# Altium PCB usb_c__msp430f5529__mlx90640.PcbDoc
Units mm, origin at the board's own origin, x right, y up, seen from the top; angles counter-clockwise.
Board outline 82 x 52 mm, 2 copper layers (Top, Bottom), stack 0 mm thick; 30 components, 24 nets, 178 pads, 53 vias.
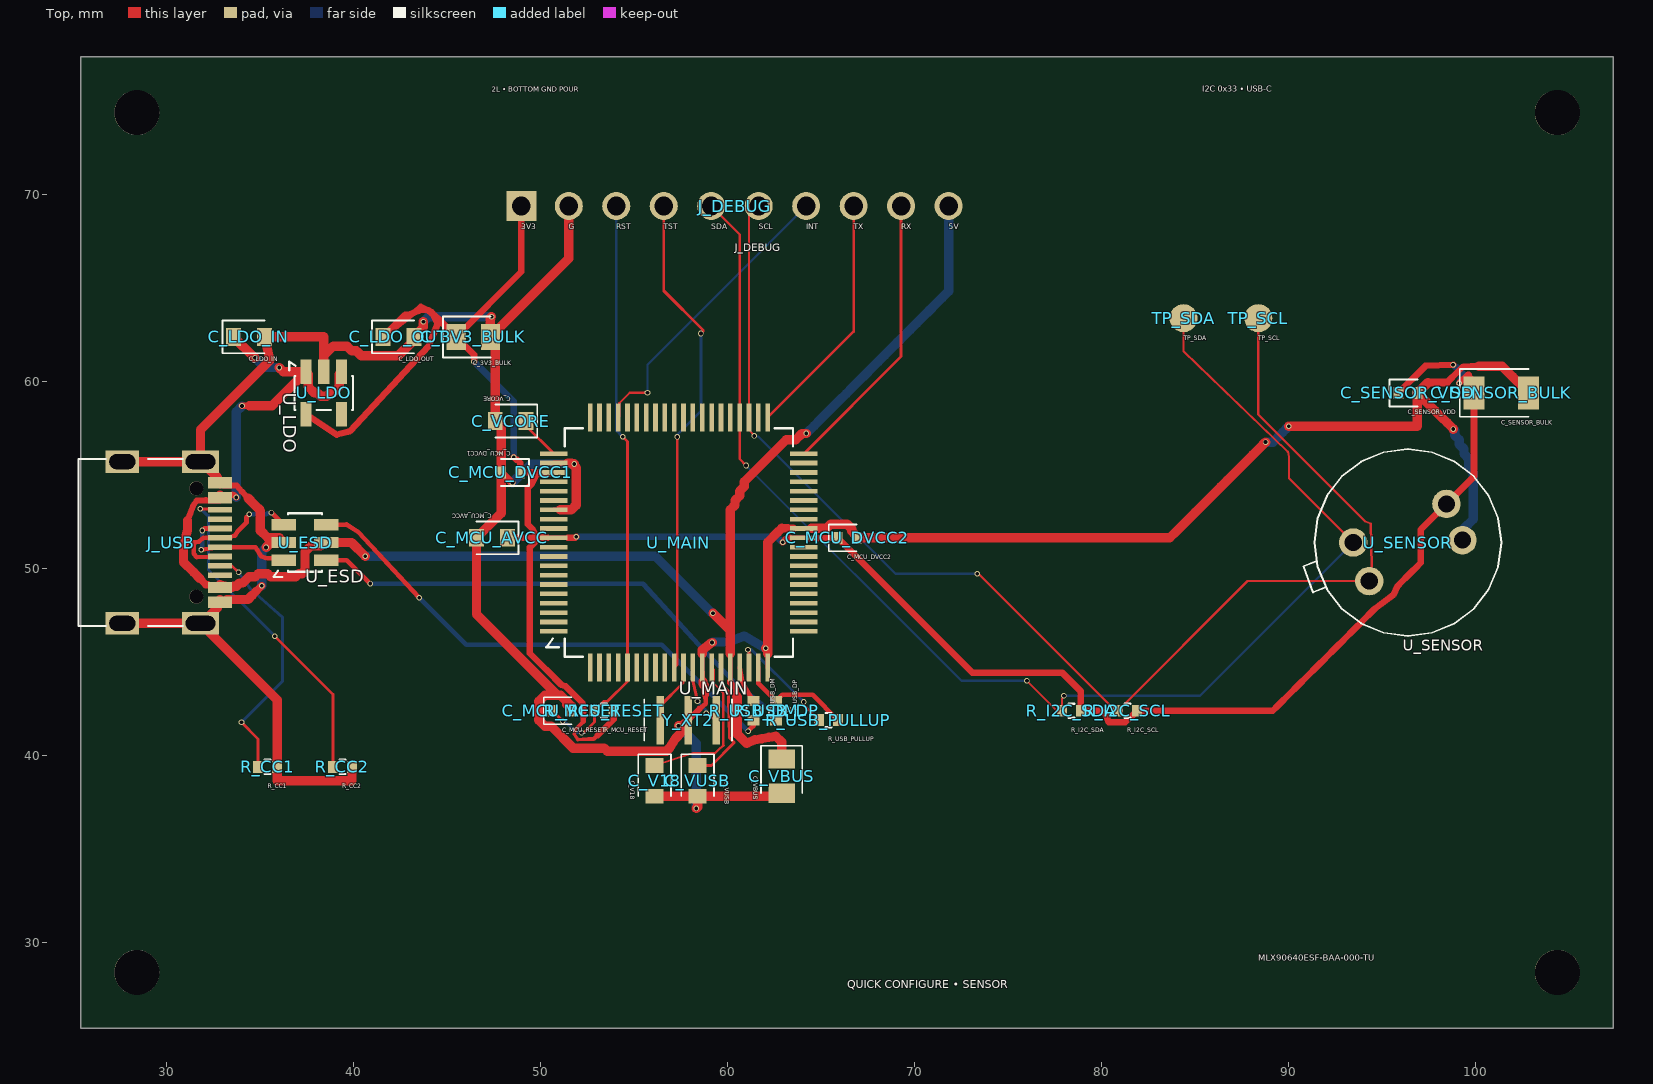
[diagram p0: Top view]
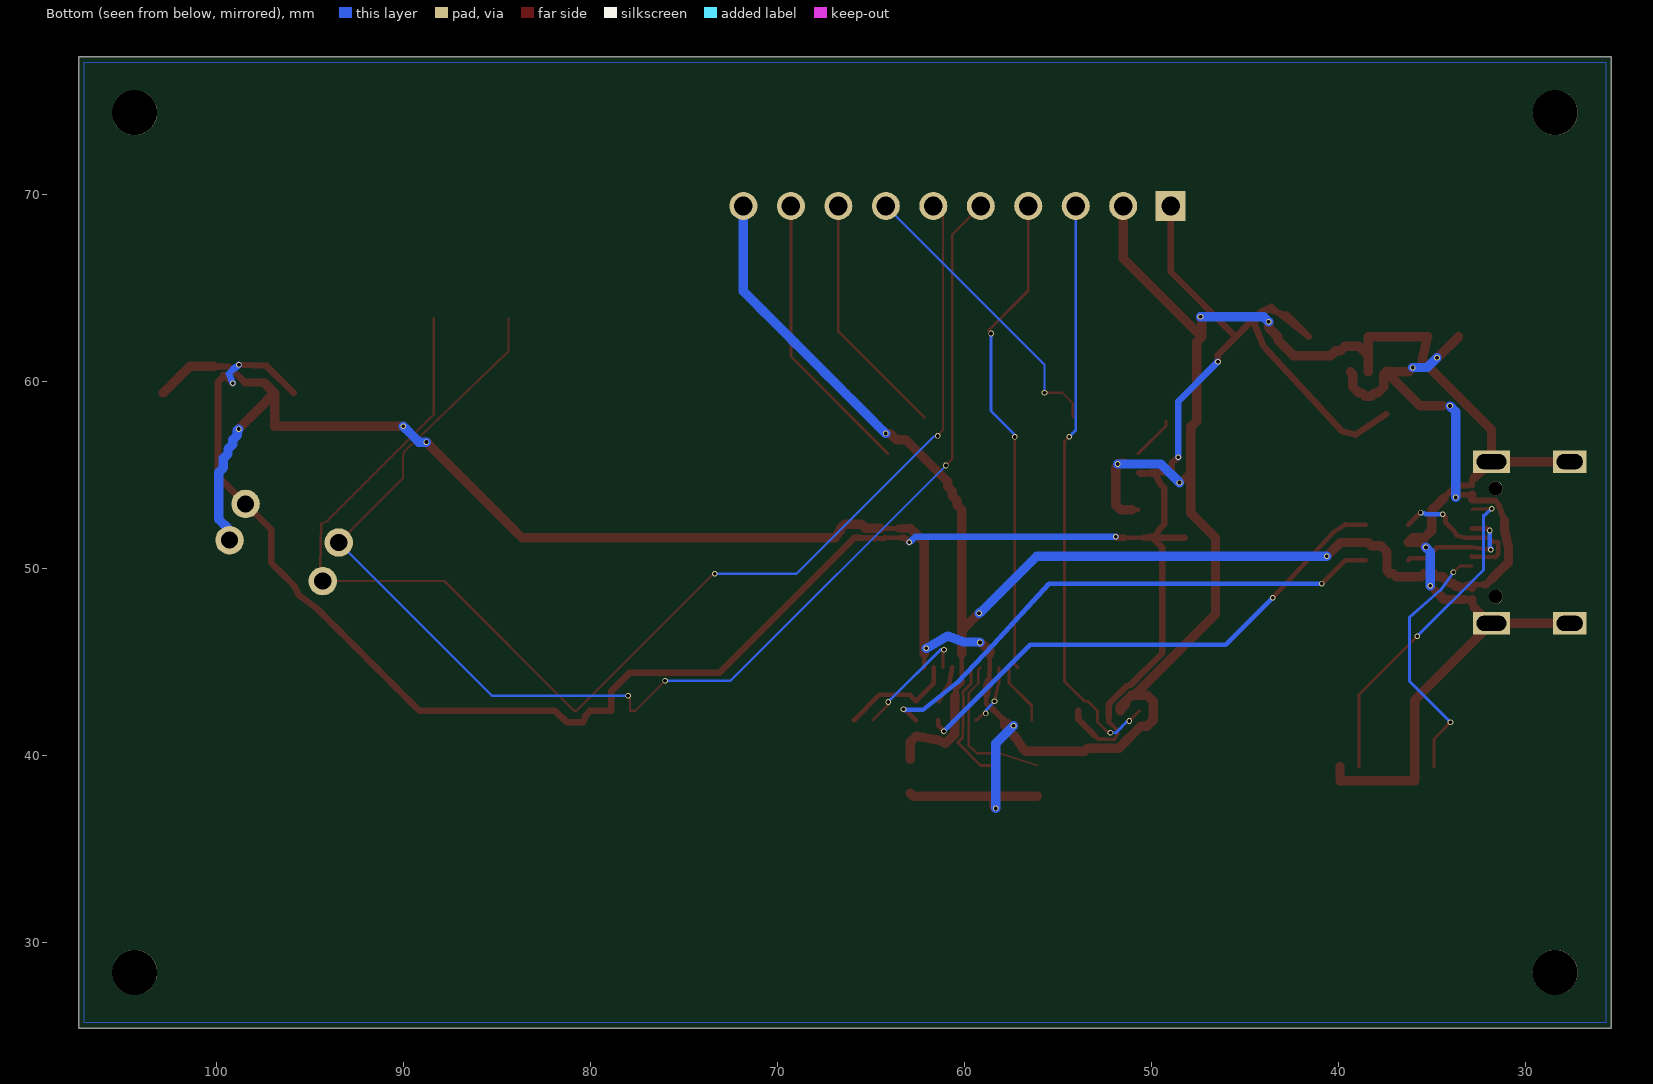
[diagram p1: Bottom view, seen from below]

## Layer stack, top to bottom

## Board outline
25.4,77.4 107.4,77.4 107.4,25.4 25.4,25.4

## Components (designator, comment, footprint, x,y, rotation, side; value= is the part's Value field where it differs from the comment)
C_3V3_BULK "" TSCIRCUIT-2.8500x1.4000mm 46.4,62.4 r0 top
C_LDO_IN "" TSCIRCUIT-2.4500x0.9500mm 34.4,62.4 r0 top
C_LDO_OUT "" TSCIRCUIT-2.4500x0.9500mm 42.4,62.4 r0 top
C_MCU_AVCC "" TSCIRCUIT-2.4500x0.9500mm 47.4,51.65 r180 top
C_MCU_DVCC1 "" TSCIRCUIT-1.5600x0.6400mm 48.4,55.15 r180 top
C_MCU_DVCC2 "" TSCIRCUIT-1.5600x0.6400mm 66.4,51.65 r0 top
C_MCU_RESET "" TSCIRCUIT-1.5600x0.6400mm 51.15,42.4 r0 top
C_SENSOR_BULK "" TSCIRCUIT-4.0500x1.7500mm 101.4,59.4 r0 top
C_SENSOR_VDD "" TSCIRCUIT-1.5600x0.6400mm 96.4,59.4 r0 top
C_V18 "" TSCIRCUIT-0.9500x2.4500mm 56.1,38.65 r270 top
C_VBUS "" TSCIRCUIT-1.4000x2.8500mm 62.9,38.9 r270 top
C_VCORE "" TSCIRCUIT-2.4500x0.9500mm 48.4,57.9 r180 top
C_VUSB "" TSCIRCUIT-0.9500x2.4500mm 58.4,38.65 r270 top
J_DEBUG "" TSCIRCUIT-24.3600x1.5000mm 60.4,69.4 r0 top
J_USB "" TSCIRCUIT-6.7732x9.8502mm 30.113,51.4 r90 top
R_CC1 "" TSCIRCUIT-1.5600x0.6400mm 35.4,39.4 r0 top
R_CC2 "" TSCIRCUIT-1.5600x0.6400mm 39.4,39.4 r0 top
R_I2C_SCL "" TSCIRCUIT-1.5600x0.6400mm 81.4,42.4 r0 top
R_I2C_SDA "" TSCIRCUIT-1.5600x0.6400mm 78.4,42.4 r0 top
R_MCU_RESET "" TSCIRCUIT-1.5600x0.6400mm 53.4,42.4 r0 top
R_USB_DM "" TSCIRCUIT-0.6400x1.5600mm 61.4,42.4 r90 top
R_USB_DP "" TSCIRCUIT-0.6400x1.5600mm 62.6,42.4 r90 top
R_USB_PULLUP "" TSCIRCUIT-1.5600x0.6400mm 65.4,41.9 r0 top
TP_SCL "" TSCIRCUIT-1.5000x1.5000mm 88.4,63.4 r0 top
TP_SDA "" TSCIRCUIT-1.5000x1.5000mm 84.4,63.4 r0 top
U_ESD "" TSCIRCUIT-3.6000x2.5000mm 37.4,51.4 r0 top
U_LDO "" TSCIRCUIT-2.5000x3.6000mm 38.4,59.4 r270 top
U_MAIN "" TSCIRCUIT-14.8500x14.8500mm 57.4,51.4 r0 top
U_SENSOR "" TSCIRCUIT-7.3640x5.6538mm 96.4,51.4 r0 top
Y_XT2 "" TSCIRCUIT-3.4000x2.6000mm 57.9,41.9 r270 top

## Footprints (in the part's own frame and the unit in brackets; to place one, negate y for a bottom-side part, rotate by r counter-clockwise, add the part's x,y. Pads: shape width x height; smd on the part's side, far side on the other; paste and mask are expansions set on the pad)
TSCIRCUIT-0.6400x1.5600mm [mm]
  rect 0.54x0.64 smd: 1(-0.51,0) 2(0.51,0)
  silkscreen extent -0.15,-0.38 0.15,0.38
TSCIRCUIT-0.9500x2.4500mm [mm]
  rect 0.8x0.95 smd: 1(-0.825,0) 2(0.825,0)
  silkscreen extent -1.43,-0.87 0.82,0.87
TSCIRCUIT-1.4000x2.8500mm [mm]
  rect 1.025x1.4 smd: 1(-0.913,0) 2(0.913,0)
  silkscreen extent -1.62,-1.1 0.91,1.1
TSCIRCUIT-1.5000x1.5000mm [mm]
  round 1.5 smd: 1(0,0)
TSCIRCUIT-1.5600x0.6400mm [mm]
  rect 0.54x0.64 smd: 1(-0.51,0) 2(0.51,0)
  silkscreen extent -0.98,-0.72 0.51,0.72
TSCIRCUIT-2.4500x0.9500mm [mm]
  rect 0.8x0.95 smd: 1(-0.825,0) 2(0.825,0)
  silkscreen extent -1.43,-0.87 0.82,0.87
TSCIRCUIT-2.5000x3.6000mm [mm]
  rect 1.325x0.6 smd: 1(-1.137,-0.95) 2(-1.137,0) 3(-1.137,0.95) 4(1.138,0.95) 5(1.138,-0.95)
  silkscreen extent -1.69,-1.84 0.91,1.56
TSCIRCUIT-2.8500x1.4000mm [mm]
  rect 1.025x1.4 smd: 1(-0.913,0) 2(0.913,0)
  silkscreen extent -1.63,-1.1 0.91,1.1
TSCIRCUIT-3.4000x2.6000mm [mm]
  rect 2.6x0.4 smd: 1(0,1.5) 2(0,0) 3(0,-1.5)
  silkscreen extent -1.1,-2.35 1.1,2.35
TSCIRCUIT-3.6000x2.5000mm [mm]
  rect 1.325x0.6 smd: 1(-1.137,-0.95) 2(-1.137,0) 3(-1.137,0.95) 4(1.138,0.95) 5(1.138,0) 6(1.138,-0.95)
  silkscreen extent -1.69,-1.84 0.91,1.56
TSCIRCUIT-4.0500x1.7500mm [mm]
  rect 1.125x1.75 smd: 1(-1.463,0) 2(1.462,0)
  silkscreen extent -2.22,-1.28 1.46,1.27
TSCIRCUIT-6.7732x9.8502mm [mm]
  rect 0.3x1.3 smd: 1(-3.35,-2.737) 2(-3.05,-2.737) 3(-2.55,-2.737) 4(-2.25,-2.737) 5(-1.75,-2.737) 6(-1.25,-2.737) 7(-0.75,-2.737) 8(-0.25,-2.737) 9(0.25,-2.737) 10(0.75,-2.737) 11(1.25,-2.737) 12(1.75,-2.737) 13(2.55,-2.737) 14(2.25,-2.737) 15(3.35,-2.737) 16(3.05,-2.737)
  rect 1.2x2 hole 0.8 slot 1.6 at 90 deg: 17(-4.325,-1.693) 18(4.325,-1.693)
  rect 1.2x1.8 hole 0.8 slot 1.4 at 90 deg: 19(4.325,2.487) 20(-4.325,2.487)
  round 0.75 hole 0.75 unplated: NPTH-1(-2.9,-1.468) NPTH-2(2.9,-1.468)
  silkscreen extent -4.47,-0.75 4.47,4.83
TSCIRCUIT-7.3640x5.6538mm [mil]
  round 60 hole 36: 1(-114.96,0) 2(81.29,81.29) 3(114.96,5) 4(-81.3,-81.3)
  silkscreen extent -220,-197 197,197
TSCIRCUIT-14.8500x14.8500mm [mm]
  rect 1.475x0.25 smd: 1(-6.687,-4.75) 2(-6.687,-4.25) 3(-6.687,-3.75) 4(-6.687,-3.25) 5(-6.687,-2.75) 6(-6.687,-2.25) 7(-6.687,-1.75) 8(-6.687,-1.25) 9(-6.687,-0.75) 10(-6.687,-0.25) 11(-6.687,0.25) 12(-6.687,0.75) 13(-6.687,1.25) 14(-6.687,1.75) 15(-6.687,2.25) 16(-6.687,2.75) 17(-6.687,3.25) 18(-6.687,3.75) 19(-6.687,4.25) 20(-6.687,4.75) 41(6.687,4.75) 42(6.687,4.25) 43(6.687,3.75) 44(6.687,3.25) 45(6.687,2.75) 46(6.687,2.25) 47(6.687,1.75) 48(6.687,1.25) 49(6.687,0.75) 50(6.687,0.25) 51(6.687,-0.25) 52(6.687,-0.75) 53(6.687,-1.25) 54(6.687,-1.75) 55(6.687,-2.25) 56(6.687,-2.75) 57(6.687,-3.25) 58(6.687,-3.75) 59(6.687,-4.25) 60(6.687,-4.75)
  rect 0.25x1.475 smd: 21(-4.75,6.687) 22(-4.25,6.687) 23(-3.75,6.687) 24(-3.25,6.687) 25(-2.75,6.687) 26(-2.25,6.687) 27(-1.75,6.687) 28(-1.25,6.687) 29(-0.75,6.687) 30(-0.25,6.687) 31(0.25,6.687) 32(0.75,6.687) 33(1.25,6.687) 34(1.75,6.687) 35(2.25,6.687) 36(2.75,6.687) 37(3.25,6.687) 38(3.75,6.687) 39(4.25,6.687) 40(4.75,6.687) 61(4.75,-6.687) 62(4.25,-6.687) 63(3.75,-6.687) 64(3.25,-6.687) 65(2.75,-6.687) 66(2.25,-6.687) 67(1.75,-6.687) 68(1.25,-6.687) 69(0.75,-6.687) 70(0.25,-6.687) 71(-0.25,-6.687) 72(-0.75,-6.687) 73(-1.25,-6.687) 74(-1.75,-6.687) 75(-2.25,-6.687) 76(-2.75,-6.687) 77(-3.25,-6.687) 78(-3.75,-6.687) 79(-4.25,-6.687) 80(-4.75,-6.687)
  silkscreen extent -7.09,-6.11 6.11,6.11
TSCIRCUIT-24.3600x1.5000mm [mm]
  rect 1.6x1.6 hole 1: 1(-11.43,0)
  round 1.5 hole 1: 2(-8.89,0) 3(-6.35,0) 4(-3.81,0) 5(-1.27,0) 6(1.27,0) 7(3.81,0) 8(6.35,0) 9(8.89,0) 10(11.43,0)

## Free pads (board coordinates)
  round 2.4 hole 2.4 unplated: NPTH-3(28.4,28.4) NPTH-4(104.4,28.4) NPTH-5(28.4,74.4) NPTH-6(104.4,74.4)

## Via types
v1: diameter 0.3, hole 0.2, Top to Bottom, 53 vias

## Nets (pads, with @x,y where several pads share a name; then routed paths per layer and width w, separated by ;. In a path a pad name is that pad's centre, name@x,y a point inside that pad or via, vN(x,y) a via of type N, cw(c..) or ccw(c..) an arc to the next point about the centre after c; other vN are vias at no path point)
".J_DEBUG > .pin4 to .U_MAIN > .pin71": J_DEBUG.4 U_MAIN.71 | length 26.2
  Top w0.15: J_DEBUG.4 56.59,64.866 58.687,62.769 58.687,62.688 v1(58.58,62.581) ; U_MAIN.71 57.311,44.873 v1(57.311,57.048)
  Bottom w0.15: v1(57.311,57.048) 57.275,57.084 57.275,57.123 58.58,58.428 v1(58.58,62.581)
".J_DEBUG > .pin8 to .U_MAIN > .pin40": J_DEBUG.8 U_MAIN.40 | length 13.2
  Top w0.15: U_MAIN.40 66.75,62.687 J_DEBUG.8
".J_DEBUG > .pin9 to .U_MAIN > .pin41": J_DEBUG.9 U_MAIN.41 | length 15.4
  Top w0.15: U_MAIN.41 69.29,61.352 J_DEBUG.9
GND: C_3V3_BULK.2 C_LDO_IN.2 C_LDO_OUT.2 C_MCU_AVCC.2 C_MCU_DVCC1.2 C_MCU_DVCC2.2 C_MCU_RESET.2 C_SENSOR_BULK.2 C_SENSOR_VDD.2 C_V18.2 C_VBUS.2 C_VCORE.2 C_VUSB.2 J_DEBUG.2 J_USB.1 J_USB.2 J_USB.15 J_USB.16 J_USB.17 J_USB.18 J_USB.19 J_USB.20 R_CC1.2 R_CC2.2 U_ESD.2 U_LDO.2 U_MAIN.14 U_MAIN.19 U_MAIN.49 U_MAIN.61 U_MAIN.68 U_SENSOR.3 Y_XT2.2 | length 203.6
  Top w0.25: U_MAIN.14 U_MAIN.14@51.053,53.15 ; 58.518,42.518 58.837,42.775 58.827,43.254 ; U_MAIN.68@58.65,45.45 58.65,45.368 58.65,45.274 58.65,45.181 58.65,45.087 58.65,44.993 58.65,44.9 58.65,44.806 U_MAIN.68 58.681,44.353 U_MAIN.68@58.681,43.975 ; U_MAIN.49@63.525,52.15 63.619,52.15 63.712,52.15 63.806,52.15 63.9,52.15 63.994,52.15 U_MAIN.49 ; U_MAIN.19 51.45,55.65 51.369,55.65 51.275,55.65 51.181,55.65 51.088,55.65 50.994,55.65 50.9,55.65 50.806,55.65 U_MAIN.19 ; U_MAIN.61 62.15,44.806 62.15,44.9 62.15,44.994 62.15,45.087 62.15,45.181 62.15,45.275 62.15,45.369 62.15,45.45 U_MAIN.61
  Top w0.269: U_MAIN.49 U_MAIN.49@64.494,52.155
  Top w0.3: J_USB.1@32.699,47.9 J_USB.1 J_USB.2@32.849,48.2 ; 32.699,54.9 J_USB.15 J_USB.16@32.849,54.6 ; J_USB.2 32.945,48.339 33.037,48.35 33.13,48.35 J_USB.2@33.224,48.35 ; J_USB.16 32.945,54.461 33.037,54.45 J_USB.16@33.318,54.45
  Top w0.31: J_USB.16 J_USB.15@32.849,54.6
  Top w0.312: J_USB.16@33.318,54.45 33.599,54.45 33.744,54.447
  Top w0.325: 33.744,54.447 34.009,54.132 34.346,53.784 ; v1@48.426,54.614 v1(48.5,54.605) ; Y_XT2.2 58.209,42.209 58.518,42.518 ; 98.784,60.251 99.077,60.538 99.37,60.825 99.784,60.826
  Top w0.35: 98.49,59.964 98.784,60.251
  Top w0.375: 58.768,43.74 58.827,43.254 ; 99.784,60.826 100.197,60.828
  Top w0.4: 34.818,48.823 35.055,49.06 v1(35.08,49.085) ; C_MCU_DVCC1.2 48.158,54.882 v1@48.426,54.614 ; 57.558,41.26 57.9,41.603 Y_XT2.2 Y_XT2.2@57.7,41.7
  Top w0.425: 97.474,59.964 98.49,59.964
  Top w0.45: 34.582,48.587 34.818,48.823 ; 63.212,52.158 U_MAIN.49@63.525,52.15
  Top w0.475: U_MAIN.68@58.681,43.975 58.681,43.826 58.768,43.74 ; 62.9,52.166 63.212,52.158
  Top w0.5: J_USB.20 J_USB.17 ; J_USB.19 J_USB.18 ; J_USB.1@32.699,47.9 32.474,47.675 31.874,47.075 J_USB.17 ; 32.699,54.9 32.474,55.125 31.874,55.725 J_USB.18 ; J_USB.1@32.849,48.2 J_USB.2 ; J_USB.2@33.224,48.35 33.598,48.35 33.972,48.35 34.345,48.35 34.582,48.587 ; 34.346,53.784 34.683,53.436 35.012,53.108 35.012,52.186 35.012,52.038 35.4,51.65 36.013,51.65 U_ESD.2 35.578,51.4 v1(35.316,51.138) ; R_CC2.2 39.91,38.65 35.91,38.65 R_CC1.2 35.91,42.971 J_USB.17 ; v1(43.732,63.208) 43.732,62.907 C_LDO_OUT.2 43.225,62.225 42.4,61.4 40.4,61.4 40.15,61.65 39.9,61.65 39.65,61.9 38.9,61.9 38.4,61.4 U_LDO.2 38.4,62.4 C_LDO_IN.2 35.525,61.15 31.806,57.431 J_USB.18 ; v1(47.375,63.475) 47.313,63.412 47.313,63.4 47.313,62.9 C_3V3_BULK.2 ; U_MAIN.14@51.053,53.15 51.65,53.15 51.9,53.4 51.9,55.4 51.65,55.65 51.45,55.65 51.463,55.65 51.663,55.65 51.698,55.615 51.785,55.615 v1(51.8,55.6) ; J_DEBUG.2 51.51,66.597 C_3V3_BULK.2 ; C_V18.2 C_VUSB.2 ; v1(57.382,41.595) 57.595,41.595 57.7,41.7 ; 57.558,41.26 57.215,40.918 56.9,40.4 56.733,40.233 53.567,40.233 53.4,40.4 51.733,40.4 50.567,41.567 50.233,41.567 49.9,41.9 49.9,42.9 50.233,43.233 51.067,43.233 ; v1(58.327,37.175) 58.4,37.248 C_VUSB.2 ; 58.65,45.45 58.65,45.462 58.65,45.525 58.65,45.65 v1(59.177,46.052) ; v1(62.044,45.737) 62.093,45.688 62.15,45.631 62.15,45.462 62.15,45.45 62.15,51.416 62.681,51.947 62.9,52.166 ; C_VBUS.2 62.737,37.825 C_VUSB.2 ; U_MAIN.49@64.494,52.155 64.9,52.16 65.301,52.16 65.525,52.384 65.962,52.384 66.4,52.384 66.655,52.129 66.655,52.017 C_MCU_DVCC2.2 67.403,51.65 67.896,51.65 68.389,51.65 68.881,51.65 69.374,51.65 69.867,51.65 70.36,51.65 70.853,51.65 71.346,51.65 71.839,51.65 72.331,51.65 72.824,51.65 73.317,51.65 73.81,51.65 74.303,51.65 74.796,51.65 75.289,51.65 75.781,51.65 76.274,51.65 76.767,51.65 77.26,51.65 77.753,51.65 78.246,51.65 78.738,51.65 79.231,51.65 79.724,51.65 80.217,51.65 80.71,51.65 81.203,51.65 81.696,51.65 82.188,51.65 82.681,51.65 83.174,51.65 83.667,51.65 84.008,51.991 84.35,52.333 84.691,52.674 85.033,53.016 85.374,53.357 85.715,53.698 86.057,54.04 86.398,54.381 86.74,54.723 87.081,55.064 87.423,55.406 87.764,55.747 88.105,56.088 88.447,56.43 v1(88.789,56.772) ; v1(90.027,57.615) 90.49,57.615 90.954,57.615 91.417,57.615 96.91,57.615 C_SENSOR_VDD.2 ; 97.474,59.964 C_SENSOR_VDD.2 ; v1(98.828,57.468) 98.828,57.482 98.508,57.802 98.189,58.121 97.869,58.441 97.549,58.761 97.23,59.08 C_SENSOR_VDD.2 ; 100.197,60.828 100.611,60.829 101.024,60.831 101.438,60.832 101.723,60.546 102.008,60.259 102.293,59.973 102.578,59.686 C_SENSOR_BULK.2 ; C_3V3_BULK.2 47.575,62.138 C_VCORE.2 47.89,57.585 C_MCU_DVCC1.2 47.89,52.965 C_MCU_AVCC.2 46.575,51.187 46.575,47.558 50.9,43.233 51.067,43.233 ; 51.067,43.233 51.66,42.64 C_MCU_RESET.2 51.66,42.473 51.4,42.733 51.4,42.9 51.067,43.233
  Bottom w0.5: v1(35.08,49.085) 35.08,50.902 v1(35.316,51.138) ; v1(43.732,63.208) 43.999,63.475 v1(47.375,63.475) ; v1(48.5,54.605) 49.495,55.6 v1(51.8,55.6) ; v1(57.382,41.595) 58.327,40.65 v1(58.327,37.175) ; v1(59.177,46.052) 59.206,46.081 60.035,46.081 60.9,46.4 v1(62.044,45.737) ; v1(88.789,56.772) 89.181,56.772 89.442,57.033 89.703,57.294 89.964,57.555 89.967,57.555 v1(90.027,57.615) ; v1(98.828,57.468) 98.896,57.4 98.9,57.4 98.9,57.15 99.15,56.9 99.15,56.65 99.4,56.4 99.4,56.15 99.65,55.9 99.65,55.4 99.9,55.15 99.9,52.65 99.4,52.15 99.4,51.9 99.32,51.82 U_SENSOR.3
MAIN_RESET: C_MCU_RESET.1 J_DEBUG.3 R_MCU_RESET.1 U_MAIN.76 | length 31.7
  Top w0.15: C_MCU_RESET.1 v1(51.188,41.852) ; v1(52.194,41.225) 52.202,41.217 52.304,41.217 52.89,41.803 R_MCU_RESET.1 53.394,42.904 53.584,42.904 54.65,43.971 U_MAIN.76 54.65,56.802 v1(54.4,57.052)
  Bottom w0.15: v1(51.188,41.852) 51.226,41.89 51.226,41.901 51.902,41.225 v1(52.194,41.225) ; J_DEBUG.3 54.05,57.408 54.232,57.226 54.232,57.22 v1(54.4,57.052)
MSP_USB_PUR: R_USB_PULLUP.1 U_MAIN.63 | length 6.4
  Top w0.15: v1(61.1,45.665) 61.15,45.631 61.15,45.462 U_MAIN.63 ; v1(64.085,42.868) 64.085,42.705 R_USB_PULLUP.1
  Bottom w0.15: v1(61.1,45.665) 61.272,45.681 63.954,42.999 63.969,42.999 v1(64.085,42.868)
MSP_V18: C_V18.1 U_MAIN.67 | length 8.4
  Top w0.12: C_V18.1 58.159,40.131 59.328,40.131 59.59,40.374 59.809,40.538 59.776,40.53 59.776,40.615 59.776,43.355 59.264,43.866 59.264,44.598 U_MAIN.67
MSP_VCORE: C_VCORE.1 U_MAIN.20 | length 2.4
  Top w0.15: C_VCORE.1 49.225,57.638 U_MAIN.20
MSP_VUSB: C_VUSB.1 U_MAIN.66 | length 6.8
  Top w0.15: C_VUSB.1 59.143,39.475 60.361,40.693 60.094,40.96 60.048,43.123 60.094,43.397 59.65,43.841 U_MAIN.66
SENSOR_INT: J_DEBUG.7 U_MAIN.24 | length 16
  Top w0.12: U_MAIN.24 54.205,58.142 54.205,58.853 54.767,59.415 v1(55.721,59.415)
  Bottom w0.12: v1(55.721,59.415) 55.723,59.417 55.723,60.913 J_DEBUG.7
SENSOR_SCL: J_DEBUG.6 R_I2C_SCL.1 TP_SCL.1 U_MAIN.38 U_SENSOR.4 | length 71.2
  Top w0.12: v1(61.428,57.104) 61.15,57.432 U_MAIN.38 61.15,68.88 J_DEBUG.6 ; v1(73.356,49.73) 73.426,49.73 80.756,42.4 R_I2C_SCL.1 87.825,49.335 U_SENSOR.4 94.45,49.4 94.45,49.5 94.45,49.6 94.45,49.699 94.45,49.798 94.45,49.893 94.45,49.988 94.45,50.097 94.465,50.098 94.411,52.422 94.126,52.522 88.4,58.249 TP_SCL.1
  Bottom w0.12: v1(61.428,57.104) 61.512,57.07 61.649,57.07 68.988,49.73 v1(73.356,49.73)
SENSOR_SDA: J_DEBUG.5 R_I2C_SDA.1 TP_SDA.1 U_MAIN.37 U_SENSOR.1 | length 72.5
  Top w0.12: J_DEBUG.5 60.65,67.88 U_MAIN.37 60.65,55.865 v1(60.995,55.52) ; v1(76.02,44) 76.043,43.977 77.62,42.4 R_I2C_SDA.1 77.89,43.043 77.966,43.119 77.966,43.166 v1(78,43.2) ; TP_SDA.1 84.4,61.626 89.98,56.26 90.04,55.986 90.04,54.84 U_SENSOR.1
  Bottom w0.12: v1(60.995,55.52) 61.03,55.485 72.515,44 v1(76.02,44) ; v1(78,43.2) 85.28,43.2 U_SENSOR.1
usb-dm-mcu: R_USB_DM.2 U_MAIN.64 | length 2
  Top w0.25: U_MAIN.64 60.818,43.844 R_USB_DM.2
usb-dm-phy: R_USB_DM.1 U_ESD.4 | length 27.9
  Top w0.25: U_ESD.4 39.619,52.365 40.242,51.962 v1(43.516,48.45) ; v1(61.103,41.306) 61.249,41.452 61.251,41.452 61.4,41.601 R_USB_DM.1
  Bottom w0.25: v1(43.516,48.45) 43.547,48.407 46.021,45.933 56.476,45.933 v1(61.103,41.306)
usb-dm-port: J_USB.7 J_USB.9 U_ESD.3 | length 8
  Top w0.25: J_USB.7 31.609,50.613 31.45,50.8 31.45,51.4 31.729,51.45 31.961,51.65 J_USB.9 33.052,51.65 33.256,51.65 33.65,51.775 33.782,51.972 33.943,52.133 34.104,52.295 34.265,52.456 34.265,52.604 34.265,52.753 34.385,52.873 v1(34.42,52.908) ; v1(35.6,53) 35.613,53 35.775,52.837 35.938,52.675 36.1,52.513 U_ESD.3
  Bottom w0.25: v1(34.42,52.908) 34.647,52.908 34.873,52.908 35.1,52.908 35.327,52.908 35.392,52.973 35.573,52.973 v1(35.6,53)
usb-dp-mcu: R_USB_DP.2 R_USB_PULLUP.2 U_MAIN.62 | length 6.2
  Top w0.25: U_MAIN.62 61.65,43.86 R_USB_DP.2 62.939,43.253 64.459,43.26 64.561,43.249 R_USB_PULLUP.2
usb-dp-phy: R_USB_DP.1 U_ESD.6 | length 29
  Top w0.25: U_ESD.6 39.633,50.45 40.803,49.28 v1(40.882,49.201) ; R_USB_DP.1 63.191,42.481 v1(63.263,42.481)
  Bottom w0.25: v1(40.882,49.201) 55.481,49.189 58.454,45.933 60.4,43.9 62.221,42.449 63.16,42.461 63.201,42.419 v1(63.263,42.481)
usb-dp-port: J_USB.8 J_USB.10 U_ESD.1 | length 6.8
  Top w0.25: v1(31.841,51.01) J_USB.8 34.751,51.144 35.046,50.673 35.347,50.55 36.158,50.555 U_ESD.1 ; v1(31.897,52.041) 32.007,52.15 32.099,52.15 32.349,52.15 32.599,52.15 J_USB.10
  Bottom w0.25: v1(31.841,51.01) 31.828,51.029 31.828,51.071 31.898,51.14 31.898,51.366 31.897,51.591 31.897,51.816 v1(31.897,52.041)
USB_CC1: J_USB.6 R_CC1.1 | length 13.8
  Top w0.15: J_USB.6 33.5,50.15 v1(33.844,49.806) ; v1(34,41.784) 34.002,41.782 34.89,40.894 R_CC1.1
  Bottom w0.15: v1(33.844,49.806) 33.917,49.733 33.917,49.681 34.525,48.858 36.193,47.405 36.193,47.374 36.193,43.977 v1(34,41.784)
USB_CC2: J_USB.12 R_CC2.1 | length 17.9
  Top w0.15: v1(31.799,53.2) 32.799,53.2 J_USB.12 ; v1(35.783,46.385) 35.799,46.369 38.89,43.278 R_CC2.1
  Bottom w0.15: v1(31.799,53.2) 31.902,53.097 31.93,53.097 32.168,52.859 32.237,52.859 32.236,49.932 v1(35.783,46.385)
VBUS5: C_LDO_IN.1 C_VBUS.1 J_DEBUG.10 J_USB.3 J_USB.4 J_USB.13 J_USB.14 U_ESD.5 U_LDO.1 U_LDO.3 U_MAIN.65 | length 96.7
  Top w0.25: U_MAIN.65@60.15,43.975 60.15,44.344 U_MAIN.65 ; U_MAIN.65 60.15,44.837 60.15,44.962 60.15,45.087 60.15,45.212 60.15,45.337 60.15,45.45 60.15,45.198 U_MAIN.65
  Top w0.275: J_USB.3 J_USB.4@32.849,49
  Top w0.3: 32.086,53.65 32.467,53.65 J_USB.14 32.849,53.8 ; J_USB.4@32.199,49.15 32.474,49.15 J_USB.4 J_USB.3@32.849,49 ; J_USB.13 32.943,53.95 33.037,53.95 33.13,53.95 33.224,53.95 33.318,53.95 33.412,53.95 33.499,53.95 ; J_USB.4@33.125,49.075 33.4,49 33.499,49
  Top w0.312: 31.261,52.966 31.409,53.357 31.608,53.64
  Top w0.325: 31.113,52.575 31.261,52.966 ; 33.59,53.941 33.606,53.938 v1(33.721,53.812) ; 60.15,43.9 60.463,43.587 60.489,43.171
  Top w0.337: 33.505,53.95 33.59,53.941
  Top w0.35: 31.608,53.64 32.086,53.65 ; 33.499,53.95 33.505,53.95 ; v1(34.027,58.707) 34.431,58.712 ; 60.15,43.9 U_MAIN.65@60.15,43.975
  Top w0.4: 31.77,49.477 32.099,49.15 J_USB.4@32.199,49.15
  Top w0.475: J_USB.4 J_USB.4@33.125,49.075 ; J_USB.13@32.849,53.8 J_USB.13
  Top w0.5: 31.113,52.575 31.113,52.086 30.9,51.15 30.9,50.345 31.44,49.805 31.442,49.805 31.77,49.477 ; 33.5,49 33.567,49.067 33.733,49.067 33.9,49.233 34.067,49.233 34.4,49.567 34.733,49.567 34.9,49.733 35.4,49.733 35.567,49.567 36.9,49.567 37.067,49.733 37.233,49.733 37.4,49.9 37.4,50.9 37.733,51.233 38.233,51.233 38.4,51.4 U_ESD.5 39.885,51.4 v1(40.62,50.664) ; C_LDO_IN.1 34.694,61.281 v1(34.724,61.281) ; 34.431,58.712 34.834,58.717 35.63,58.717 U_LDO.1 ; v1(36.014,60.759) 36.034,60.739 36.236,60.537 U_LDO.1 ; U_LDO.3 39.35,60.517 39.233,60.4 39.233,59.733 38.9,59.4 38.733,59.4 38.567,59.233 38.233,59.233 38.067,59.4 37.9,59.4 37.567,59.733 37.567,60.4 37.4,60.567 37.421,60.567 U_LDO.1 ; v1(59.221,47.617) 60.15,46.688 60.15,45.712 60.15,45.587 60.15,45.462 60.15,45.45 60.15,45.684 60.15,46.17 60.15,46.655 60.15,47.141 60.15,47.627 60.15,48.113 60.15,48.598 60.15,49.084 60.15,49.57 60.15,50.055 60.15,50.541 60.15,51.027 60.15,51.513 60.15,51.998 60.15,52.484 60.15,52.97 60.15,53.15 60.4,53.4 60.4,53.65 60.65,53.9 60.65,54.15 60.9,54.4 60.9,54.65 63.15,56.9 63.65,56.9 63.985,57.235 v1(64.22,57.235) ; 60.489,43.171 60.525,43.134 60.525,41.15 61.025,40.65 61.462,40.841 61.836,40.907 62.21,40.973 62.584,41.039 62.9,40.724 62.9,40.268 C_VBUS.1
  Bottom w0.5: v1(33.721,53.812) 33.721,58.401 v1(34.027,58.707) ; v1(34.724,61.281) 35.245,60.759 v1(36.014,60.759) ; v1(40.62,50.664) 56.134,50.67 59.132,47.671 59.167,47.671 v1(59.221,47.617) ; v1(64.22,57.235) 64.294,57.309 64.637,57.652 64.979,57.994 65.322,58.337 65.664,58.679 66.007,59.022 66.349,59.364 66.692,59.707 67.034,60.049 67.377,60.392 67.72,60.735 68.062,61.077 68.405,61.42 68.747,61.762 69.09,62.105 69.432,62.447 69.775,62.79 70.117,63.132 70.46,63.475 70.802,63.817 71.145,64.16 71.487,64.502 71.83,64.845 71.83,65.3 71.83,65.756 71.83,66.212 71.83,66.667 71.83,67.122 71.83,67.578 71.83,68.034 71.83,68.489 71.83,68.945 J_DEBUG.10
VCC_3V3: C_3V3_BULK.1 C_LDO_OUT.1 C_MCU_AVCC.1 C_MCU_DVCC1.1 C_MCU_DVCC2.1 C_SENSOR_BULK.1 C_SENSOR_VDD.1 J_DEBUG.1 R_I2C_SCL.2 R_I2C_SDA.2 R_MCU_RESET.2 U_LDO.5 U_MAIN.11 U_MAIN.18 U_MAIN.50 U_SENSOR.2 | length 134.1
  Top w0.175: 51.8,41.15 51.9,41 52,40.85
  Top w0.188: 52,40.85 52.262,40.88
  Top w0.2: 51.8,41.15 51.854,41.392 52.073,41.611 ; 52.262,40.88 52.555,40.88
  Top w0.212: 52.073,41.611 52.293,41.83
  Top w0.225: 52.555,40.88 52.848,40.88 53.061,41.092
  Top w0.25: U_MAIN.18@49.975,55.075 U_MAIN.18@50.125,55.075 ; U_MAIN.18@49.975,55.15 50.056,55.15 50.15,55.15 50.244,55.15 50.337,55.15 50.431,55.15 50.525,55.15 50.619,55.15 U_MAIN.18 50.589,55.027 50.356,55.027 U_MAIN.18@50.343,55.054 ; U_MAIN.11@49.976,51.65 50.057,51.65 50.15,51.65 50.244,51.65 50.338,51.65 50.432,51.65 50.525,51.65 50.619,51.65 U_MAIN.11 ; U_MAIN.11@50.194,51.65 50.453,51.65 U_MAIN.11 ; U_MAIN.11@50.376,51.65 U_MAIN.11 ; 51.45,51.65 51.369,51.65 51.275,51.65 51.181,51.65 51.088,51.65 50.994,51.65 50.9,51.65 50.806,51.65 U_MAIN.11 ; U_MAIN.50@63.351,51.65 63.432,51.65 63.525,51.65 63.619,51.65 63.713,51.65 63.807,51.65 63.9,51.65 63.994,51.65 U_MAIN.50 64.182,51.65 U_MAIN.50@64.276,51.65
  Top w0.29: U_MAIN.50@64.276,51.65 64.37,51.608 U_MAIN.50@64.825,51.621
  Top w0.3: U_MAIN.18@50.125,55.075 U_MAIN.18@50.343,55.054 ; 52.293,41.83 52.293,42.089
  Top w0.35: U_LDO.5 39.1,57.175 39.8,57.35 44,61.9 44.5,63.1 44.2,63.7 43.6,64 C_LDO_OUT.1 41.81,62.638 42.045,62.876 42.281,63.114 42.516,63.352 42.751,63.59 43.038,63.617 43.6,63.85 44,63.825 44.547,63.359 44.782,63.12 45.017,62.88 45.252,62.64 C_3V3_BULK.1 ; v1(46.441,61.077) 46.441,61.447 C_3V3_BULK.1 ; C_MCU_AVCC.1 49.963,51.65 49.975,51.65 ; v1(48.571,55.956) 48.695,55.832 48.746,55.832 48.91,55.668 C_MCU_DVCC1.1 49.963,55.15 U_MAIN.18@49.975,55.15 ; J_DEBUG.1 48.97,65.882 C_3V3_BULK.1 ; 49.975,55.075 49.775,55.075 49.51,54.515 49.313,54.318 49.313,53.994 49.313,53.671 49.313,53.347 49.313,53.023 49.313,52.7 49.313,52.376 49.555,52.134 49.775,51.75 U_MAIN.11@50.376,51.65 ; U_MAIN.11@50.194,51.65 49.934,51.65 49.764,51.48 49.594,51.31 49.424,51.14 49.424,50.806 49.424,50.473 49.424,50.14 49.424,49.807 49.424,49.473 49.424,49.14 49.424,48.807 49.424,48.474 49.424,48.141 49.424,47.807 49.424,47.474 49.424,47.141 49.424,46.808 49.424,46.474 49.424,46.141 49.424,45.808 49.424,45.475 49.663,45.236 49.902,44.997 50.141,44.758 50.38,44.519 50.619,44.28 50.858,44.04 51.097,43.801 51.35,43.7 52.225,42.825 52.293,42.606 52.293,42.347 52.293,42.089 ; 51.45,51.65 51.463,51.65 51.713,51.65 51.859,51.65 v1(51.914,51.705) ; 53.061,41.092 53.273,41.305 53.485,41.517 53.698,41.73 53.91,41.942 53.91,42.171 R_MCU_RESET.2 ; v1(62.962,51.414) 63.163,51.626 63.338,51.65 63.35,51.65 ; 64.825,51.621 65.62,51.643 C_MCU_DVCC2.1 73.1,44.44 77.903,44.44 78.91,43.433 R_I2C_SDA.2 79.192,42.4 79.473,42.4 79.755,42.4 80.036,42.4 80.254,42.164 80.4,41.775 81.275,41.775 81.468,42.01 81.52,42.01 81.715,42.205 R_I2C_SCL.2 82.256,42.4 82.602,42.4 82.948,42.4 83.294,42.4 83.64,42.4 83.986,42.4 84.331,42.4 84.677,42.4 85.023,42.4 85.369,42.4 85.715,42.4 86.061,42.4 86.407,42.4 86.753,42.4 87.099,42.4 87.445,42.4 87.791,42.4 88.137,42.4 88.483,42.4 88.828,42.4 89.174,42.4 89.422,42.647 89.669,42.895 89.917,43.142 90.164,43.39 90.411,43.637 90.659,43.884 90.906,44.132 91.154,44.379 91.401,44.627 91.649,44.874 91.896,45.122 92.143,45.369 92.391,45.616 92.638,45.864 92.886,46.111 93.133,46.359 93.38,46.606 93.628,46.853 93.875,47.101 94.123,47.348 94.37,47.596 94.617,47.843 95.625,48.6 95.855,49.08 96.102,49.328 96.349,49.575 96.597,49.822 96.844,50.07 97.092,50.317 97.092,50.613 97.092,50.909 97.092,51.204 97.092,51.5 97.092,51.796 97.092,52.092 97.32,52.32 97.549,52.549 97.778,52.778 98.007,53.007 98.236,53.236 U_SENSOR.2 99.938,54.938 C_SENSOR_BULK.1 99.937,59.984 99.643,60.278 99.643,60.377 v1(99.15,59.925) ; C_SENSOR_VDD.1 97.336,60.846 v1(98.819,60.907)
  Bottom w0.35: v1(46.441,61.077) 46.462,61.056 48.571,58.947 v1(48.571,55.956) ; v1(51.914,51.705) 62.631,51.705 62.831,51.506 62.841,51.506 v1(62.962,51.414) ; v1(98.819,60.907) 98.943,60.783 99.003,60.783 99.358,60.428 v1(99.15,59.925)
XT2_IN: U_MAIN.69 Y_XT2.1 | length 3.4
  Top w0.15: U_MAIN.69 58.159,44.703 58.159,43.968 v1(58.393,42.913) ; v1(58.866,42.256) 58.909,42.213 59.03,42.213 59.343,41.9 Y_XT2.1
  Bottom w0.15: v1(58.393,42.913) 58.446,42.86 58.446,42.831 58.866,42.411 v1(58.866,42.256)
XT2_OUT: U_MAIN.70 Y_XT2.3 | length 3.3
  Top w0.15: Y_XT2.3 56.4,42.665 57.627,43.892 57.627,44.689 U_MAIN.70
pads on no net: J_USB.5 J_USB.11 J_USB.NPTH-1 J_USB.NPTH-2 U_LDO.4 U_MAIN.1 U_MAIN.2 U_MAIN.3 U_MAIN.4 U_MAIN.5 U_MAIN.6 U_MAIN.7 U_MAIN.8 U_MAIN.9 U_MAIN.10 U_MAIN.12 U_MAIN.13 U_MAIN.15 U_MAIN.16 U_MAIN.17 U_MAIN.21 U_MAIN.22 U_MAIN.23 U_MAIN.25 U_MAIN.26 U_MAIN.27 U_MAIN.28 U_MAIN.29 U_MAIN.30 U_MAIN.31 U_MAIN.32 U_MAIN.33 U_MAIN.34 U_MAIN.35 U_MAIN.36 U_MAIN.39 U_MAIN.42 U_MAIN.43 U_MAIN.44 U_MAIN.45 U_MAIN.46 U_MAIN.47 U_MAIN.48 U_MAIN.51 U_MAIN.52 U_MAIN.53 U_MAIN.54 U_MAIN.55 U_MAIN.56 U_MAIN.57 U_MAIN.58 U_MAIN.59 U_MAIN.60 U_MAIN.72 U_MAIN.73 U_MAIN.74 U_MAIN.75 U_MAIN.77 U_MAIN.78 U_MAIN.79 U_MAIN.80

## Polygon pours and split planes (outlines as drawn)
GND on Bottom (solid): 107.1,77.1 25.7,77.1 25.7,25.7 107.1,25.7

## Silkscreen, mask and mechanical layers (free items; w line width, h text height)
Top Overlay:
  text "2L • BOTTOM GND POUR" at 47.4,75.4 h0.48
  text "I2C 0x33 • USB-C" at 85.4,75.4 h0.55
  text "MLX90640ESF-BAA-000-TU" at 88.4,28.9 h0.58
  text "QUICK CONFIGURE • SENSOR" at 66.4,27.4 h0.72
